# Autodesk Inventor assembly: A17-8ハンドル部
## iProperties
Created: 2008-07
Part Number: A17-8ハンドル部
Document SubType Name: Assembly
Designer: y-shimohigashi
Stock Number: A17-8ハンドル部
Author: y-shimohigashi
